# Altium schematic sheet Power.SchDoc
size A4; SheetNumber: 1; SheetTotal: 4
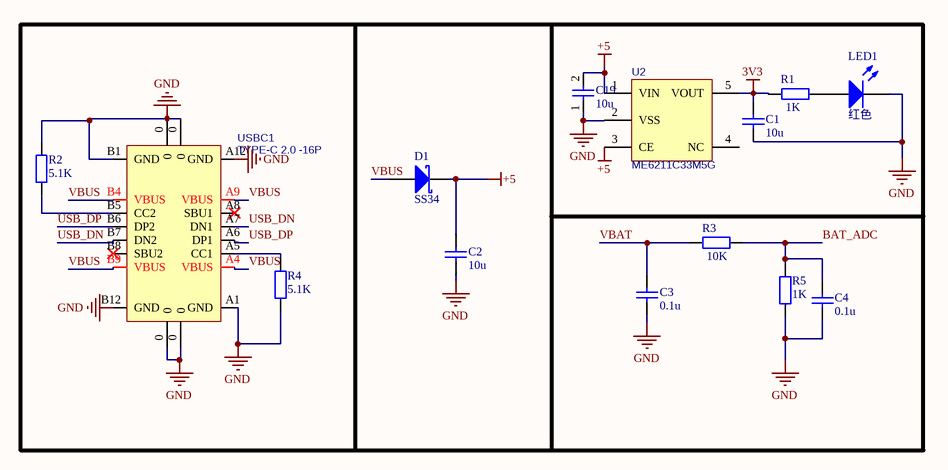
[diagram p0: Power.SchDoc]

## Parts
C1  10u  [C0402_M]
C2  10u  [C0402_M]
C3  0.1u  [C0402_M]
C4  0.1u  [C0402_M]
C19  10u  [C0402_M]
D1  SS34  [SOD-123]
LED1  红色  [LED0603_R]
R1  1K  [R0402_M]
R2  5.1K  [R0402_M]
R3  10K  [R0402_M]
R4  5.1K  [R0402_M]
R5  1K  [R0402_M]
U2  ME6211C33M5G  [SOT-23-5]
USBC1  TYPE-C 2.0 -16P  [USB-C-SMD_16P]

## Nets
3V3: C1.2 R1.1 U2.5(VOUT)
+5: C2.2 C19.2 D1.2(K) U2.1(VIN) U2.3(CE)
GND: C1.1 C2.1 C3.1 C4.2 C19.1 LED1.2(K) R2.2 R4.1 R5.1 U2.2(VSS) USBC1.0 USBC1.A1(GND) USBC1.A12(GND) USBC1.B1(GND) USBC1.B12(GND)
BAT_ADC: C4.1 R3.2 R5.2
USB_DN: USBC1.A7(DN1) USBC1.B7(DN2)
USB_DP: USBC1.A6(DP1) USBC1.B6(DP2)
VBAT: C3.2 R3.1
VBUS: D1.1(A) USBC1.A4(VBUS) USBC1.A9(VBUS) USBC1.B4(VBUS) USBC1.B9(VBUS)
NetLED1_1: LED1.1(A) R1.2
NetR2_1: R2.1 USBC1.B5(CC2)
NetR4_2: R4.2 USBC1.A5(CC1)

Not connected (* = marked no-connect by the designer): U2 4(NC); USBC1 A8(SBU1)* B8(SBU2)*

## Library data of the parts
C1-C4 C19 = C: 贴片电容/MLCC电容; BOM名称: 无极性贴片电容; 当前库版本V2022.12.25 @淘宝卖家:黄晶宝石: 最新版本发布https://shop463601444.taobao.com
D1 = SS34: 肖特基二极管; 属性: 40V/3A; 当前库版本V2022.12.25 @淘宝卖家:黄晶宝石: 最新版本发布https://shop463601444.taobao.com
LED1 = LED: 贴片LED; 封装库来自淘宝卖家：黄晶宝石: 其他店铺购入均为盗版封装库，无更新权益，请立即申请退款，本店现金奖励200~1000元
R1-R5 = R: 贴片电阻; 联系下单店铺卖家 免费帮你查找封装: 联系下单店铺卖家 免费技术支持
U2 = ME6211C33: LDO 3.3V/0.5A; BOM名称: RT9193-30GB; 当前库版本V2022.12.25 @淘宝卖家:黄晶宝石: 最新版本发布https://shop463601444.taobao.com
USBC1 = USB2.0_Type-C_16Pin: USB2.0_Type-C_16Pin母座; 当前库版本V2022.12.25 @淘宝卖家:黄晶宝石: 最新版本发布https://shop463601444.taobao.com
